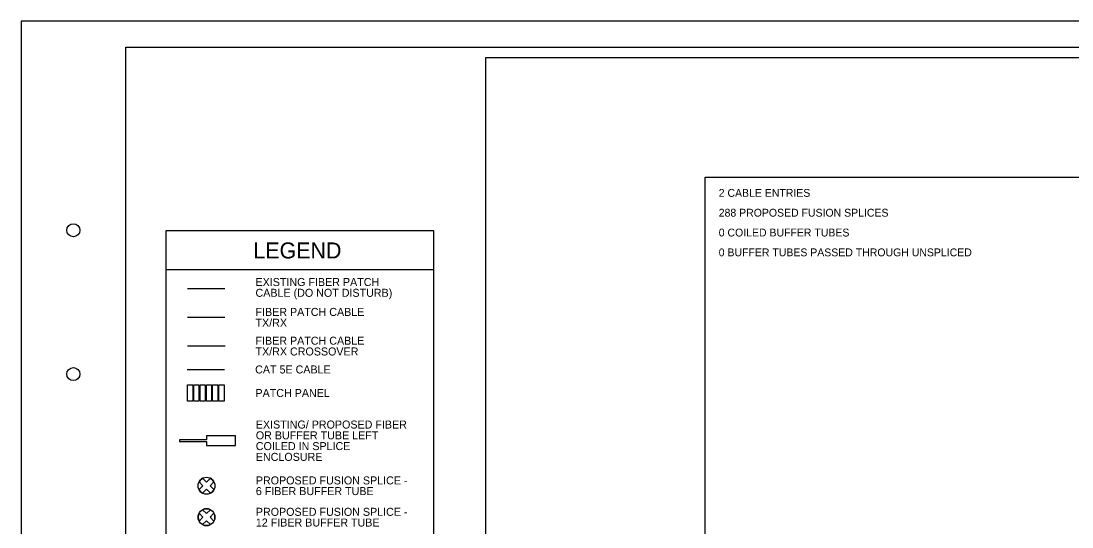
# Model space of a CAD drawing. Extents: x 1805893 to 1833564, y 708898 to 716199.
# Drawn here: x 1831322.5 to 1831724.2, y 715501.7 to 715695.2 of the extents above; entities that cross this region are included whole.
import ezdxf

# ---------------------------------------------------------------- set-up
doc = ezdxf.new("R2010")
doc.units = 0
for name, color, linetype in [('BR_P_Sub_Hidden', 7, 'Continuous'), ('SH_Border', 7, 'Continuous'), ('SH_Cut_Line', 7, 'Continuous'), ('SH_Data', 7, 'Continuous')]:
    doc.layers.add(name, color=color, linetype=linetype)

msp = doc.modelspace()

# ---------------------------------------------------------------- linework, layer by layer
at = {"layer": 'BR_P_Sub_Hidden'}
for points in [[(1831500.15, 715681.19), (1831958.68, 715681.19), (1831958.68, 715270.69), (1831500.15, 715270.69)], [(1831583.98, 715635.5), (1831928.32, 715635.5), (1831928.32, 715312.36), (1831583.98, 715312.36)]]:
    msp.add_lwpolyline(points, close=True, dxfattribs=at)
at = {"layer": 'SH_Border'}
msp.add_lwpolyline([(1831362.49, 715685.17), (1831992.49, 715685.17), (1831992.49, 715265.17), (1831362.49, 715265.17)], close=True, dxfattribs=at)
for centre in [(1831342.49, 715615.17), (1831342.49, 715560.17)]:
    msp.add_circle(centre, 2.5, dxfattribs=at)
at = {"layer": 'SH_Cut_Line'}
msp.add_lwpolyline([(1831322.49, 715255.17), (1832002.49, 715255.17), (1832002.49, 715695.17), (1831322.49, 715695.17)], close=True, dxfattribs=at)
at = {"layer": 'SH_Data'}
for p, q in [((1831386.09, 715592.89), (1831400.43, 715592.89)), ((1831386.09, 715581.88), (1831400.43, 715581.88)), ((1831392.03, 715517.48), (1831390.54, 715518.97)), ((1831390.54, 715518.97), (1831392.03, 715517.48)), ((1831393.39, 715518.84), (1831391.9, 715520.33)), ((1831393.39, 715518.84), (1831391.9, 715520.33)), ((1831393.39, 715518.84), (1831394.88, 715520.33)), ((1831394.88, 715520.33), (1831393.39, 715518.84)), ((1831394.75, 715517.48), (1831396.24, 715518.97)), ((1831394.75, 715517.48), (1831396.24, 715518.97)), ((1831390.54, 715515.99), (1831392.03, 715517.48)), ((1831392.03, 715517.48), (1831390.54, 715515.99)), ((1831391.9, 715514.63), (1831393.39, 715516.13)), ((1831391.9, 715514.63), (1831393.39, 715516.13)), ((1831394.88, 715514.63), (1831393.39, 715516.13)), ((1831393.39, 715516.13), (1831394.88, 715514.63)), ((1831396.24, 715515.99), (1831394.75, 715517.48)), ((1831396.24, 715515.99), (1831394.75, 715517.48)), ((1831392.03, 715505.47), (1831390.54, 715506.97)), ((1831392.03, 715505.47), (1831390.54, 715506.97)), ((1831393.39, 715506.83), (1831391.9, 715508.32)), ((1831391.9, 715508.32), (1831393.39, 715506.83)), ((1831393.39, 715506.83), (1831394.88, 715508.32)), ((1831393.39, 715506.83), (1831394.88, 715508.32)), ((1831394.75, 715505.47), (1831396.24, 715506.97)), ((1831396.24, 715506.97), (1831394.75, 715505.47)), ((1831390.54, 715503.98), (1831392.03, 715505.47)), ((1831390.54, 715503.98), (1831392.03, 715505.47)), ((1831391.9, 715502.63), (1831393.39, 715504.12)), ((1831393.39, 715504.12), (1831391.9, 715502.63)), ((1831394.88, 715502.63), (1831393.39, 715504.12)), ((1831394.88, 715502.63), (1831393.39, 715504.12)), ((1831396.24, 715503.98), (1831394.75, 715505.47)), ((1831394.75, 715505.47), (1831396.24, 715503.98))]:
    msp.add_line(p, q, dxfattribs=at)
for points in [[(1831377.93, 715615.12), (1831480.16, 715615.12), (1831480.16, 715600), (1831377.93, 715600)], [(1831480.16, 715615.12), (1831480.16, 715424.95), (1831377.93, 715424.95), (1831377.93, 715615.12)], [(1831388.1, 715556.07), (1831388.1, 715549.82), (1831386.14, 715549.82), (1831386.14, 715556.07)], [(1831390.49, 715556.07), (1831390.49, 715549.82), (1831388.53, 715549.82), (1831388.53, 715556.07)], [(1831392.89, 715556.07), (1831392.89, 715549.82), (1831390.93, 715549.82), (1831390.93, 715556.07)], [(1831395.28, 715556.07), (1831395.28, 715549.82), (1831393.32, 715549.82), (1831393.32, 715556.07)], [(1831397.68, 715556.07), (1831397.68, 715549.82), (1831395.72, 715549.82), (1831395.72, 715556.07)], [(1831400.07, 715556.07), (1831400.07, 715549.82), (1831398.11, 715549.82), (1831398.11, 715556.07)]]:
    msp.add_lwpolyline(points, close=True, dxfattribs=at)
for points in [[(1831400.46, 715570.88), (1831386.09, 715570.88), (1831386.09, 715570.88), (1831386.09, 715570.88)], [(1831385.95, 715561.94), (1831400.29, 715561.97), (1831400.29, 715561.97)], [(1831383.09, 715535.01), (1831383.09, 715534.7), (1831383.09, 715534.39), (1831393.38, 715534.39), (1831393.38, 715532.87), (1831404.43, 715532.87), (1831404.43, 715536.54), (1831393.38, 715536.54), (1831393.38, 715535.01), (1831383.09, 715535.01)], [(1831404.43, 715532.87), (1831404.43, 715536.54), (1831393.38, 715536.54), (1831393.38, 715535.01), (1831383.09, 715535.01), (1831383.09, 715534.7), (1831383.09, 715534.39), (1831393.38, 715534.39), (1831393.38, 715532.87), (1831404.43, 715532.87)]]:
    msp.add_lwpolyline(points, dxfattribs=at)
for centre in [(1831393.39, 715517.48), (1831393.39, 715505.47)]:
    msp.add_circle(centre, 3.22, dxfattribs=at)
for centre, start, end in [((1831393.39, 715517.48), 117.647, 152.353), ((1831393.39, 715517.48), 27.647, 62.353), ((1831393.39, 715517.48), 207.647, 242.353), ((1831393.39, 715517.48), 297.647, 332.353), ((1831393.39, 715505.47), 152.353, 207.647), ((1831393.39, 715505.47), 62.353, 117.647), ((1831393.39, 715505.47), 332.353, 27.647), ((1831393.39, 715505.47), 242.353, 297.647)]:
    msp.add_arc(centre, 3.22, start, end, dxfattribs=at)

# ---------------------------------------------------------------- texts
for s, height, p in [('2 CABLE ENTRIES', 3, (1831589.15, 715627.95)), ('288 PROPOSED FUSION SPLICES', 3, (1831589.15, 715620.37)), ('0 COILED BUFFER TUBES', 3, (1831589.15, 715612.79)), ('LEGEND', 6.119, (1831411.3, 715604.39)), ('0 BUFFER TUBES PASSED THROUGH UNSPLICED', 3, (1831589.15, 715605.21)), ('EXISTING FIBER PATCH ', 3.0596, (1831412.11, 715593.84)), ('CABLE (DO NOT DISTURB)', 3.0596, (1831412.11, 715589.72)), ('FIBER PATCH CABLE', 3.0596, (1831412.11, 715582.41)), ('TX/RX', 3.06, (1831412.11, 715578.29)), ('FIBER PATCH CABLE', 3.0596, (1831412.11, 715571.41)), ('TX/RX CROSSOVER', 3.0596, (1831412.11, 715567.29)), ('CAT 5E CABLE', 3.0596, (1831411.97, 715560.41)), ('PATCH PANEL', 3.0596, (1831412.09, 715551.41)), ('EXISTING/ PROPOSED FIBER ', 3.0596, (1831412.23, 715539.35)), ('OR BUFFER TUBE LEFT ', 3.0596, (1831412.23, 715535.23)), ('COILED IN SPLICE ', 3.0596, (1831412.23, 715531.11)), ('ENCLOSURE', 3.06, (1831412.23, 715526.99)), ('PROPOSED FUSION SPLICE - ', 3.0596, (1831412.24, 715517.99)), ('6 FIBER BUFFER TUBE', 3.0596, (1831412.24, 715513.91)), ('PROPOSED FUSION SPLICE - ', 3.0596, (1831412.24, 715505.98)), ('12 FIBER BUFFER TUBE', 3.0596, (1831412.24, 715501.9))]:
    msp.add_text(s, height=height, dxfattribs=at).set_placement(p)

doc.saveas('drawing.dxf')
